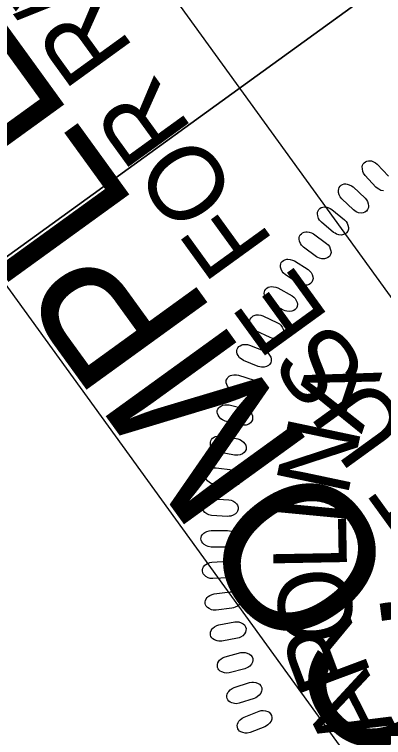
# Model space of a CAD drawing. Extents: x 474248 to 476123, y 501895 to 503900.
# Drawn here: x 474393.9 to 474422.4, y 503181.5 to 503237.4 of the extents above; entities that cross this region are included whole.
import ezdxf

# ---------------------------------------------------------------- set-up
doc = ezdxf.new("R2010")
doc.units = 0
for name, color, linetype in [('Sheet PE Seal Cell', 7, 'Continuous'), ('Sheet Plan CELL', 7, 'Continuous'), ('Sheet Sticker Incomplete CELL', 7, 'Continuous')]:
    doc.layers.add(name, color=color, linetype=linetype)

msp = doc.modelspace()

# ---------------------------------------------------------------- linework, layer by layer
at = {"layer": 'Sheet PE Seal Cell'}
msp.add_lwpolyline([(474422.356, 503223.738), (474422.153, 503223.78), (474421.981, 503223.866), (474421.87, 503223.94), (474421.771, 503224.024), (474420.933, 503224.92), (474420.811, 503225.106), (474420.753, 503225.244), (474420.719, 503225.444), (474420.715, 503225.591), (474420.742, 503225.725), (474420.791, 503225.826), (474420.86, 503225.917), (474420.955, 503225.979), (474421.064, 503226.039), (474421.181, 503226.067), (474421.325, 503226.065), (474421.423, 503226.048), (474421.575, 503225.984), (474421.742, 503225.894), (474421.867, 503225.793), (474422.731, 503224.881)], dxfattribs=at)
for points in [[(474420.028, 503222.271), (474419.136, 503223.113), (474419.002, 503223.291), (474418.936, 503223.424), (474418.89, 503223.622), (474418.877, 503223.768), (474418.895, 503223.905), (474418.938, 503224.008), (474419.001, 503224.104), (474419.092, 503224.171), (474419.197, 503224.238), (474419.311, 503224.273), (474419.456, 503224.28), (474419.555, 503224.27), (474419.71, 503224.216), (474419.882, 503224.136), (474420.013, 503224.043), (474420.933, 503223.186), (474421.04, 503223.053), (474421.111, 503222.925), (474421.165, 503222.75), (474421.19, 503222.573), (474421.182, 503222.448), (474421.118, 503222.292), (474421.029, 503222.17), (474420.898, 503222.089), (474420.79, 503222.047), (474420.63, 503222.022), (474420.425, 503222.052), (474420.247, 503222.126), (474420.133, 503222.194)], [(474418.501, 503220.536), (474417.558, 503221.321), (474417.414, 503221.489), (474417.339, 503221.618), (474417.28, 503221.814), (474417.258, 503221.958), (474417.268, 503222.095), (474417.304, 503222.201), (474417.361, 503222.3), (474417.448, 503222.374), (474417.548, 503222.447), (474417.659, 503222.489), (474417.803, 503222.506), (474417.903, 503222.501), (474418.061, 503222.457), (474418.238, 503222.388), (474418.375, 503222.304), (474419.346, 503221.506), (474419.462, 503221.381), (474419.541, 503221.257), (474419.606, 503221.086), (474419.642, 503220.911), (474419.641, 503220.785), (474419.587, 503220.626), (474419.507, 503220.498), (474419.381, 503220.409), (474419.276, 503220.36), (474419.118, 503220.326), (474418.911, 503220.342), (474418.73, 503220.406), (474418.611, 503220.466)], [(474417.178, 503218.659), (474416.187, 503219.382), (474416.032, 503219.542), (474415.949, 503219.666), (474415.879, 503219.857), (474415.847, 503220), (474415.849, 503220.137), (474415.878, 503220.245), (474415.929, 503220.348), (474416.011, 503220.426), (474416.106, 503220.505), (474416.215, 503220.555), (474416.358, 503220.58), (474416.457, 503220.582), (474416.619, 503220.548), (474416.798, 503220.491), (474416.941, 503220.415), (474417.96, 503219.68), (474418.084, 503219.562), (474418.17, 503219.443), (474418.246, 503219.277), (474418.293, 503219.104), (474418.3, 503218.978), (474418.256, 503218.816), (474418.184, 503218.684), (474418.063, 503218.587), (474417.962, 503218.532), (474417.806, 503218.487), (474417.599, 503218.491), (474417.414, 503218.542), (474417.292, 503218.594)], [(474415.816, 503216.594), (474414.782, 503217.253), (474414.617, 503217.403), (474414.527, 503217.521), (474414.444, 503217.707), (474414.404, 503217.848), (474414.397, 503217.986), (474414.42, 503218.095), (474414.463, 503218.201), (474414.541, 503218.284), (474414.63, 503218.369), (474414.736, 503218.425), (474414.877, 503218.46), (474414.976, 503218.468), (474415.139, 503218.444), (474415.323, 503218.398), (474415.469, 503218.331), (474416.533, 503217.662), (474416.664, 503217.552), (474416.757, 503217.439), (474416.843, 503217.277), (474416.901, 503217.108), (474416.916, 503216.983), (474416.882, 503216.818), (474416.818, 503216.682), (474416.705, 503216.577), (474416.606, 503216.516), (474416.454, 503216.462), (474416.247, 503216.453), (474416.059, 503216.492), (474415.934, 503216.537)], [(474414.64, 503214.533), (474413.566, 503215.126), (474413.393, 503215.265), (474413.295, 503215.378), (474413.201, 503215.558), (474413.152, 503215.697), (474413.136, 503215.833), (474413.152, 503215.944), (474413.189, 503216.052), (474413.261, 503216.14), (474413.345, 503216.23), (474413.447, 503216.293), (474413.586, 503216.337), (474413.684, 503216.351), (474413.848, 503216.337), (474414.034, 503216.302), (474414.184, 503216.245), (474415.288, 503215.644), (474415.425, 503215.542), (474415.526, 503215.435), (474415.622, 503215.28), (474415.69, 503215.114), (474415.713, 503214.991), (474415.69, 503214.824), (474415.635, 503214.683), (474415.528, 503214.572), (474415.433, 503214.505), (474415.285, 503214.441), (474415.078, 503214.419), (474414.888, 503214.447), (474414.761, 503214.484)], [(474413.602, 503212.415), (474412.493, 503212.939), (474412.311, 503213.067), (474412.207, 503213.173), (474412.101, 503213.347), (474412.044, 503213.482), (474412.02, 503213.618), (474412.029, 503213.73), (474412.059, 503213.839), (474412.125, 503213.932), (474412.203, 503214.027), (474412.301, 503214.096), (474412.436, 503214.149), (474412.534, 503214.168), (474412.698, 503214.165), (474412.886, 503214.142), (474413.04, 503214.095), (474414.179, 503213.564), (474414.323, 503213.471), (474414.43, 503213.371), (474414.535, 503213.221), (474414.613, 503213.061), (474414.645, 503212.938), (474414.631, 503212.771), (474414.585, 503212.627), (474414.486, 503212.509), (474414.396, 503212.436), (474414.251, 503212.363), (474414.047, 503212.328), (474413.855, 503212.344), (474413.725, 503212.373)], [(474412.681, 503210.191), (474411.542, 503210.645), (474411.351, 503210.761), (474411.241, 503210.861), (474411.125, 503211.028), (474411.059, 503211.159), (474411.026, 503211.292), (474411.028, 503211.405), (474411.051, 503211.516), (474411.111, 503211.613), (474411.183, 503211.713), (474411.277, 503211.788), (474411.409, 503211.848), (474411.505, 503211.874), (474411.67, 503211.881), (474411.858, 503211.87), (474412.014, 503211.832), (474413.185, 503211.375), (474413.334, 503211.291), (474413.447, 503211.197), (474413.562, 503211.055), (474413.65, 503210.899), (474413.689, 503210.779), (474413.686, 503210.611), (474413.649, 503210.465), (474413.557, 503210.341), (474413.472, 503210.262), (474413.332, 503210.181), (474413.13, 503210.133), (474412.938, 503210.137), (474412.807, 503210.157)], [(474411.926, 503207.915), (474410.761, 503208.297), (474410.564, 503208.401), (474410.447, 503208.493), (474410.32, 503208.653), (474410.247, 503208.78), (474410.206, 503208.91), (474410.2, 503209.023), (474410.216, 503209.136), (474410.27, 503209.236), (474410.336, 503209.34), (474410.425, 503209.421), (474410.552, 503209.489), (474410.647, 503209.522), (474410.81, 503209.539), (474410.999, 503209.54), (474411.158, 503209.512), (474412.355, 503209.128), (474412.508, 503209.054), (474412.628, 503208.968), (474412.751, 503208.833), (474412.849, 503208.683), (474412.895, 503208.566), (474412.903, 503208.398), (474412.875, 503208.25), (474412.791, 503208.12), (474412.711, 503208.036), (474412.577, 503207.946), (474412.378, 503207.885), (474412.187, 503207.877), (474412.054, 503207.889)], [(474411.307, 503205.664), (474410.119, 503205.971), (474409.916, 503206.063), (474409.794, 503206.148), (474409.658, 503206.299), (474409.576, 503206.421), (474409.527, 503206.549), (474409.514, 503206.661), (474409.523, 503206.774), (474409.571, 503206.878), (474409.63, 503206.986), (474409.714, 503207.073), (474409.837, 503207.149), (474409.929, 503207.187), (474410.091, 503207.214), (474410.279, 503207.227), (474410.439, 503207.209), (474411.658, 503206.901), (474411.816, 503206.837), (474411.94, 503206.758), (474412.072, 503206.631), (474412.179, 503206.488), (474412.232, 503206.374), (474412.251, 503206.207), (474412.232, 503206.057), (474412.156, 503205.923), (474412.082, 503205.834), (474411.954, 503205.736), (474411.759, 503205.662), (474411.569, 503205.642), (474411.436, 503205.646)], [(474410.837, 503203.334), (474409.633, 503203.566), (474409.425, 503203.645), (474409.297, 503203.722), (474409.152, 503203.864), (474409.063, 503203.98), (474409.006, 503204.105), (474408.986, 503204.216), (474408.987, 503204.33), (474409.029, 503204.436), (474409.081, 503204.548), (474409.159, 503204.64), (474409.277, 503204.724), (474409.367, 503204.767), (474409.526, 503204.805), (474409.713, 503204.83), (474409.875, 503204.822), (474411.11, 503204.59), (474411.272, 503204.537), (474411.401, 503204.466), (474411.54, 503204.348), (474411.656, 503204.211), (474411.717, 503204.101), (474411.746, 503203.935), (474411.737, 503203.784), (474411.67, 503203.645), (474411.601, 503203.552), (474411.479, 503203.446), (474411.289, 503203.361), (474411.1, 503203.329), (474410.967, 503203.324)], [(474410.489, 503200.928), (474409.272, 503201.084), (474409.059, 503201.149), (474408.927, 503201.219), (474408.773, 503201.352), (474408.676, 503201.462), (474408.612, 503201.583), (474408.585, 503201.692), (474408.58, 503201.806), (474408.614, 503201.914), (474408.659, 503202.029), (474408.731, 503202.126), (474408.844, 503202.217), (474408.931, 503202.266), (474409.088, 503202.313), (474409.273, 503202.35), (474409.434, 503202.352), (474410.682, 503202.199), (474410.847, 503202.155), (474410.98, 503202.093), (474411.126, 503201.984), (474411.251, 503201.855), (474411.318, 503201.748), (474411.357, 503201.585), (474411.358, 503201.434), (474411.299, 503201.291), (474411.236, 503201.194), (474411.121, 503201.08), (474410.938, 503200.983), (474410.751, 503200.94), (474410.619, 503200.927)], [(474410.301, 503198.605), (474409.077, 503198.685), (474408.861, 503198.736), (474408.725, 503198.797), (474408.562, 503198.92), (474408.459, 503199.024), (474408.387, 503199.141), (474408.354, 503199.248), (474408.342, 503199.362), (474408.368, 503199.472), (474408.406, 503199.589), (474408.473, 503199.69), (474408.579, 503199.788), (474408.662, 503199.843), (474408.816, 503199.899), (474408.999, 503199.948), (474409.16, 503199.96), (474410.414, 503199.886), (474410.582, 503199.853), (474410.719, 503199.799), (474410.872, 503199.699), (474411.004, 503199.578), (474411.078, 503199.476), (474411.127, 503199.315), (474411.137, 503199.165), (474411.088, 503199.018), (474411.031, 503198.917), (474410.923, 503198.797), (474410.747, 503198.689), (474410.562, 503198.633), (474410.431, 503198.612)], [(474410.265, 503196.24), (474409.038, 503196.242), (474408.819, 503196.28), (474408.679, 503196.333), (474408.51, 503196.445), (474408.401, 503196.543), (474408.321, 503196.654), (474408.281, 503196.76), (474408.261, 503196.872), (474408.281, 503196.984), (474408.312, 503197.103), (474408.372, 503197.208), (474408.472, 503197.312), (474408.552, 503197.372), (474408.701, 503197.439), (474408.881, 503197.499), (474409.041, 503197.521), (474410.297, 503197.525), (474410.467, 503197.502), (474410.606, 503197.457), (474410.766, 503197.368), (474410.905, 503197.255), (474410.985, 503197.158), (474411.044, 503197.001), (474411.064, 503196.851), (474411.024, 503196.702), (474410.973, 503196.597), (474410.874, 503196.47), (474410.704, 503196.351), (474410.524, 503196.284), (474410.394, 503196.255)], [(474410.406, 503193.874), (474409.182, 503193.799), (474408.961, 503193.823), (474408.819, 503193.867), (474408.642, 503193.968), (474408.526, 503194.058), (474408.44, 503194.166), (474408.394, 503194.267), (474408.367, 503194.379), (474408.38, 503194.491), (474408.404, 503194.612), (474408.456, 503194.721), (474408.55, 503194.831), (474408.626, 503194.896), (474408.771, 503194.972), (474408.947, 503195.043), (474409.104, 503195.075), (474410.358, 503195.159), (474410.529, 503195.146), (474410.671, 503195.11), (474410.835, 503195.03), (474410.982, 503194.927), (474411.068, 503194.835), (474411.137, 503194.682), (474411.165, 503194.534), (474411.135, 503194.383), (474411.091, 503194.275), (474411, 503194.141), (474410.838, 503194.012), (474410.663, 503193.934), (474410.535, 503193.896)], [(474410.653, 503191.512), (474409.436, 503191.36), (474409.214, 503191.37), (474409.069, 503191.405), (474408.887, 503191.495), (474408.766, 503191.578), (474408.673, 503191.68), (474408.62, 503191.779), (474408.587, 503191.887), (474408.593, 503192.001), (474408.608, 503192.123), (474408.654, 503192.235), (474408.74, 503192.351), (474408.812, 503192.42), (474408.952, 503192.506), (474409.123, 503192.587), (474409.278, 503192.629), (474410.525, 503192.791), (474410.696, 503192.79), (474410.84, 503192.763), (474411.009, 503192.693), (474411.162, 503192.599), (474411.253, 503192.513), (474411.332, 503192.364), (474411.37, 503192.218), (474411.349, 503192.065), (474411.312, 503191.955), (474411.228, 503191.816), (474411.075, 503191.677), (474410.905, 503191.588), (474410.78, 503191.542)], [(474411.077, 503189.196), (474409.871, 503188.968), (474409.649, 503188.964), (474409.502, 503188.99), (474409.314, 503189.069), (474409.189, 503189.143), (474409.09, 503189.239), (474409.031, 503189.335), (474408.99, 503189.441), (474408.99, 503189.555), (474408.996, 503189.678), (474409.036, 503189.792), (474409.115, 503189.913), (474409.182, 503189.987), (474409.317, 503190.081), (474409.482, 503190.173), (474409.634, 503190.225), (474410.868, 503190.465), (474411.038, 503190.474), (474411.184, 503190.456), (474411.358, 503190.397), (474411.516, 503190.313), (474411.612, 503190.232), (474411.7, 503190.089), (474411.747, 503189.946), (474411.736, 503189.792), (474411.706, 503189.68), (474411.632, 503189.536), (474411.487, 503189.388), (474411.323, 503189.288), (474411.202, 503189.235)], [(474411.634, 503186.833), (474410.446, 503186.53), (474410.224, 503186.512), (474410.076, 503186.528), (474409.883, 503186.595), (474409.753, 503186.662), (474409.648, 503186.751), (474409.584, 503186.843), (474409.536, 503186.946), (474409.529, 503187.059), (474409.528, 503187.183), (474409.56, 503187.299), (474409.631, 503187.426), (474409.694, 503187.503), (474409.822, 503187.605), (474409.981, 503187.708), (474410.13, 503187.769), (474411.346, 503188.086), (474411.516, 503188.106), (474411.662, 503188.097), (474411.839, 503188.049), (474412.002, 503187.975), (474412.103, 503187.901), (474412.2, 503187.763), (474412.256, 503187.623), (474412.254, 503187.469), (474412.232, 503187.355), (474412.167, 503187.207), (474412.031, 503187.05), (474411.875, 503186.94), (474411.756, 503186.879)], [(474412.378, 503184.552), (474411.211, 503184.175), (474410.99, 503184.143), (474410.842, 503184.151), (474410.645, 503184.205), (474410.512, 503184.264), (474410.401, 503184.346), (474410.331, 503184.433), (474410.277, 503184.534), (474410.262, 503184.647), (474410.254, 503184.77), (474410.279, 503184.888), (474410.341, 503185.018), (474410.399, 503185.099), (474410.521, 503185.209), (474410.673, 503185.321), (474410.818, 503185.392), (474412.012, 503185.785), (474412.18, 503185.816), (474412.327, 503185.816), (474412.506, 503185.78), (474412.673, 503185.715), (474412.779, 503185.648), (474412.884, 503185.517), (474412.949, 503185.38), (474412.957, 503185.226), (474412.942, 503185.111), (474412.886, 503184.96), (474412.762, 503184.794), (474412.611, 503184.674), (474412.497, 503184.606)], [(474413.194, 503182.365), (474412.052, 503181.915), (474411.835, 503181.87), (474411.685, 503181.867), (474411.486, 503181.909), (474411.349, 503181.96), (474411.234, 503182.035), (474411.158, 503182.118), (474411.098, 503182.215), (474411.076, 503182.326), (474411.06, 503182.449), (474411.077, 503182.568), (474411.132, 503182.701), (474411.184, 503182.786), (474411.299, 503182.904), (474411.444, 503183.026), (474411.584, 503183.106), (474412.751, 503183.572), (474412.917, 503183.613), (474413.063, 503183.622), (474413.244, 503183.597), (474413.415, 503183.544), (474413.525, 503183.483), (474413.638, 503183.359), (474413.711, 503183.227), (474413.729, 503183.073), (474413.721, 503182.958), (474413.675, 503182.803), (474413.561, 503182.629), (474413.418, 503182.502), (474413.309, 503182.426)]]:
    msp.add_lwpolyline(points, close=True, dxfattribs=at)
at = {"layer": 'Sheet Plan CELL'}
msp.add_line((474365.666, 503198.69), (474456.749, 503264.656), dxfattribs=at)
for points in [[(474365.666, 503198.69), (474307.015, 503279.669), (474398.139, 503345.665), (474456.797, 503264.676)], [(474424.343, 503117.653), (474365.666, 503198.69), (474456.797, 503264.676), (474515.447, 503183.634)]]:
    msp.add_lwpolyline(points, close=True, dxfattribs=at)
at = {"layer": 'Sheet Sticker Incomplete CELL'}
msp.add_lwpolyline([(474454.332, 503172.147), (474435.298, 503158.364), (474349.086, 503277.429), (474368.12, 503291.211)], close=True, dxfattribs=at)

# ---------------------------------------------------------------- texts
at = {"layer": 'Sheet PE Seal Cell'}
for s, rotation, p in [('A', 71.5767, (474420.665, 503204.93)), ('N', 78.066, (474419.55, 503200.024)), ('I', 84.5554, (474419.458, 503197.729)), ('L', 91.0447, (474419.537, 503194.461)), ('O', 97.5341, (474420.262, 503189.143)), ('R', 110.5128, (474421.465, 503186.366)), ('A', 117.0022, (474423.288, 503182.493)), ('C', 123.4915, (474425.803, 503178.665))]:
    msp.add_text(s, height=5.669, rotation=rotation, dxfattribs=at).set_placement(p)
at = {"layer": 'Sheet Plan CELL'}
msp.add_text('ROADWAY DESIGN', height=5.0001, rotation=125.9074, dxfattribs=at).set_placement((474418.893, 503137.627))
at = {"layer": 'Sheet Sticker Incomplete CELL'}
for s, height, p in [('INCOMPLETE PLANS', 11.52, (474439.607, 503172.534)), ('DO NOT USE FOR R/W ACQUISITION', 5.76, (474443.33, 503179.242))]:
    msp.add_text(s, height=height, rotation=125.9074, dxfattribs=at).set_placement(p)

doc.saveas('drawing.dxf')
